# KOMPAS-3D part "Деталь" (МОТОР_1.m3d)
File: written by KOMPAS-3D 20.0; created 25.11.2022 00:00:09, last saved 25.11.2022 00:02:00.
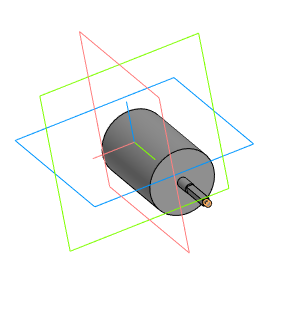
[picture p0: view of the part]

Document properties: Полное имя файла: C:\Users\Семья\Desktop\ДЕТАЛИ ДЛЯ СБОРЩИКА БОРЩЕВИКА\МОТОР_1.m3d

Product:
- Part/product: Деталь
    Масса: 0.0746701
  - Body: Тело 1
      Масса: 0.0745964

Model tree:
1. Эскиз:1
2. Элемент выдавливания:1
     Расстояние 1 = 30
3. Эскиз:2  (with: Элемент выдавливания:1)
4. Элемент выдавливания:2
     Расстояние 1 = 10
5. Элемент выдавливания:3  (with: Элемент выдавливания:2)
     Расстояние 2 = 5
6. Эскиз:3  (with: Элемент выдавливания:3)
7. Элемент выдавливания:4
     Расстояние 1 = 10
8. Эскиз:4  (with: Элемент выдавливания:4)
9. Элемент выдавливания:5
     Расстояние 1 = 1.5
10. Условное изображение резьбы:1  (with: Элемент выдавливания:5)  (labels: M2; cil0_24705-2004 coarse)
     Длина резьбы = 1.5; Шаг резьбы = 0.4; Номинальный диаметр резьбы = 2
11. Подгонка:1  (with: Элемент выдавливания:5)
